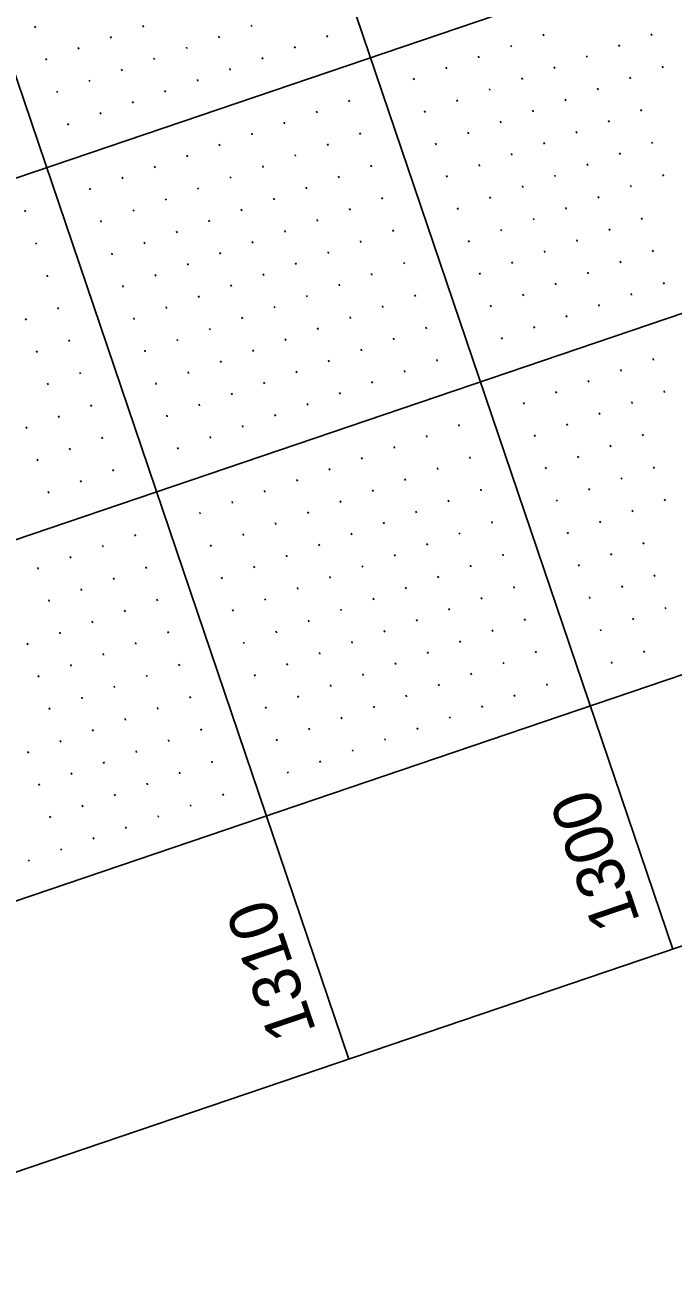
# Model space of a CAD drawing. Extents: x 2150318 to 2152065, y 143281 to 145371.
# Drawn here: x 2151548.2 to 2151642.9, y 143675.5 to 143858.1 of the extents above; entities that cross this region are included whole.
import ezdxf

# ---------------------------------------------------------------- set-up
doc = ezdxf.new("R2010")
doc.units = 0
for name, color, linetype in [('SHT_Plan_Profile_Sheet_Elev_Txt', 7, 'Continuous'), ('SHT_Profile_Grid_Major', 7, 'Continuous'), ('SHT_Profile_Grid_Minor', 7, 'Continuous'), ('SHT_Sheet_Border', 7, 'Continuous')]:
    doc.layers.add(name, color=color, linetype=linetype)

msp = doc.modelspace()

# ---------------------------------------------------------------- linework, layer by layer
at = {"layer": 'SHT_Profile_Grid_Major'}
for p, q in [((2151642.87, 143723.15), (2151136.88, 145214.66)), ((2151595.52, 143707.09), (2151089.53, 145198.6)), ((2151835.44, 143933.68), (2151361.94, 143773.05)), ((2151851.5, 143886.33), (2151378.01, 143725.7))]:
    msp.add_line(p, q, dxfattribs=at)
at = {"layer": 'SHT_Profile_Grid_Minor'}
for p, q in [((2151549.69, 143857.73), (2151549.61, 143857.97)), ((2151565.5, 143857.81), (2151565.42, 143858.05)), ((2151581.32, 143857.9), (2151581.23, 143858.14)), ((2151639.82, 143856.63), (2151639.74, 143856.86)), ((2151560.77, 143856.21), (2151560.69, 143856.44)), ((2151576.58, 143856.29), (2151576.5, 143856.53)), ((2151592.39, 143856.38), (2151592.31, 143856.61)), ((2151619.28, 143854.94), (2151619.2, 143855.17)), ((2151624.01, 143856.54), (2151623.93, 143856.78)), ((2151635.09, 143855.02), (2151635.01, 143855.26)), ((2151551.3, 143853), (2151551.22, 143853.23)), ((2151556.03, 143854.6), (2151555.95, 143854.84)), ((2151567.11, 143853.08), (2151567.03, 143853.32)), ((2151571.85, 143854.69), (2151571.76, 143854.92)), ((2151582.92, 143853.16), (2151582.84, 143853.4)), ((2151587.66, 143854.77), (2151587.58, 143855.01)), ((2151614.54, 143853.33), (2151614.46, 143853.57)), ((2151630.35, 143853.42), (2151630.27, 143853.65)), ((2151562.38, 143851.47), (2151562.3, 143851.71)), ((2151578.19, 143851.56), (2151578.11, 143851.79)), ((2151609.81, 143851.72), (2151609.73, 143851.96)), ((2151625.62, 143851.81), (2151625.54, 143852.05)), ((2151641.43, 143851.89), (2151641.35, 143852.13)), ((2151557.64, 143849.87), (2151557.56, 143850.1)), ((2151573.45, 143849.95), (2151573.37, 143850.19)), ((2151605.07, 143850.12), (2151604.99, 143850.36)), ((2151620.89, 143850.2), (2151620.8, 143850.44)), ((2151636.7, 143850.29), (2151636.62, 143850.52)), ((2151552.91, 143848.26), (2151552.83, 143848.5)), ((2151568.72, 143848.34), (2151568.64, 143848.58)), ((2151616.15, 143848.6), (2151616.07, 143848.83)), ((2151631.96, 143848.68), (2151631.88, 143848.92)), ((2151563.98, 143846.74), (2151563.9, 143846.97)), ((2151595.6, 143846.91), (2151595.52, 143847.14)), ((2151611.42, 143846.99), (2151611.33, 143847.23)), ((2151627.23, 143847.07), (2151627.15, 143847.31)), ((2151559.25, 143845.13), (2151559.17, 143845.37)), ((2151590.87, 143845.3), (2151590.79, 143845.54)), ((2151606.68, 143845.38), (2151606.6, 143845.62)), ((2151617.76, 143843.86), (2151617.68, 143844.1)), ((2151622.49, 143845.47), (2151622.41, 143845.7)), ((2151633.57, 143843.95), (2151633.49, 143844.18)), ((2151638.3, 143845.55), (2151638.22, 143845.79)), ((2151554.51, 143843.53), (2151554.43, 143843.76)), ((2151581.4, 143842.09), (2151581.32, 143842.32)), ((2151586.13, 143843.69), (2151586.05, 143843.93)), ((2151597.21, 143842.17), (2151597.13, 143842.41)), ((2151613.02, 143842.26), (2151612.94, 143842.49)), ((2151628.83, 143842.34), (2151628.75, 143842.58)), ((2151576.66, 143840.48), (2151576.58, 143840.72)), ((2151592.48, 143840.56), (2151592.4, 143840.8)), ((2151608.29, 143840.65), (2151608.21, 143840.89)), ((2151624.1, 143840.73), (2151624.02, 143840.97)), ((2151639.91, 143840.82), (2151639.83, 143841.05)), ((2151571.93, 143838.87), (2151571.85, 143839.11)), ((2151587.74, 143838.96), (2151587.66, 143839.2)), ((2151619.36, 143839.13), (2151619.28, 143839.36)), ((2151635.17, 143839.21), (2151635.09, 143839.45)), ((2151567.19, 143837.27), (2151567.11, 143837.5)), ((2151583.01, 143837.35), (2151582.93, 143837.59)), ((2151598.82, 143837.44), (2151598.74, 143837.67)), ((2151614.63, 143837.52), (2151614.55, 143837.76)), ((2151630.44, 143837.6), (2151630.36, 143837.84)), ((2151562.46, 143835.66), (2151562.38, 143835.9)), ((2151578.27, 143835.75), (2151578.19, 143835.98)), ((2151594.08, 143835.83), (2151594, 143836.07)), ((2151609.89, 143835.91), (2151609.81, 143836.15)), ((2151625.7, 143836), (2151625.62, 143836.23)), ((2151641.52, 143836.08), (2151641.43, 143836.32)), ((2151557.72, 143834.06), (2151557.64, 143834.29)), ((2151573.54, 143834.14), (2151573.46, 143834.38)), ((2151589.35, 143834.22), (2151589.27, 143834.46)), ((2151620.97, 143834.39), (2151620.89, 143834.63)), ((2151632.05, 143832.87), (2151631.96, 143833.11)), ((2151636.78, 143834.48), (2151636.7, 143834.71)), ((2151568.8, 143832.53), (2151568.72, 143832.77)), ((2151584.61, 143832.62), (2151584.53, 143832.85)), ((2151595.69, 143831.09), (2151595.61, 143831.33)), ((2151600.42, 143832.7), (2151600.34, 143832.94)), ((2151611.5, 143831.18), (2151611.42, 143831.42)), ((2151616.23, 143832.79), (2151616.15, 143833.02)), ((2151627.31, 143831.26), (2151627.23, 143831.5)), ((2151548.25, 143830.84), (2151548.17, 143831.08)), ((2151559.33, 143829.32), (2151559.25, 143829.56)), ((2151564.07, 143830.93), (2151563.99, 143831.16)), ((2151575.14, 143829.4), (2151575.06, 143829.64)), ((2151579.88, 143831.01), (2151579.8, 143831.25)), ((2151590.95, 143829.49), (2151590.87, 143829.73)), ((2151622.58, 143829.66), (2151622.5, 143829.89)), ((2151638.39, 143829.74), (2151638.31, 143829.98)), ((2151570.41, 143827.8), (2151570.33, 143828.03)), ((2151586.22, 143827.88), (2151586.14, 143828.12)), ((2151602.03, 143827.97), (2151601.95, 143828.2)), ((2151617.84, 143828.05), (2151617.76, 143828.29)), ((2151633.65, 143828.13), (2151633.57, 143828.37)), ((2151549.86, 143826.11), (2151549.78, 143826.34)), ((2151565.67, 143826.19), (2151565.59, 143826.43)), ((2151581.48, 143826.28), (2151581.4, 143826.51)), ((2151597.29, 143826.36), (2151597.21, 143826.6)), ((2151613.11, 143826.44), (2151613.03, 143826.68)), ((2151628.92, 143826.53), (2151628.84, 143826.76)), ((2151560.94, 143824.59), (2151560.86, 143824.82)), ((2151576.75, 143824.67), (2151576.67, 143824.91)), ((2151592.56, 143824.75), (2151592.48, 143824.99)), ((2151624.18, 143824.92), (2151624.1, 143825.16)), ((2151639.99, 143825.01), (2151639.91, 143825.24)), ((2151572.01, 143823.06), (2151571.93, 143823.3)), ((2151587.82, 143823.15), (2151587.74, 143823.38)), ((2151603.64, 143823.23), (2151603.56, 143823.47)), ((2151619.45, 143823.32), (2151619.37, 143823.55)), ((2151635.26, 143823.4), (2151635.18, 143823.64)), ((2151551.47, 143821.37), (2151551.39, 143821.61)), ((2151567.28, 143821.46), (2151567.2, 143821.69)), ((2151583.09, 143821.54), (2151583.01, 143821.78)), ((2151598.9, 143821.62), (2151598.82, 143821.86)), ((2151614.71, 143821.71), (2151614.63, 143821.95)), ((2151625.79, 143820.19), (2151625.71, 143820.42)), ((2151630.52, 143821.79), (2151630.44, 143822.03)), ((2151641.6, 143820.27), (2151641.52, 143820.51)), ((2151562.54, 143819.85), (2151562.46, 143820.09)), ((2151573.62, 143818.33), (2151573.54, 143818.57)), ((2151578.35, 143819.93), (2151578.27, 143820.17)), ((2151589.43, 143818.41), (2151589.35, 143818.65)), ((2151594.17, 143820.02), (2151594.09, 143820.26)), ((2151605.24, 143818.5), (2151605.16, 143818.73)), ((2151621.05, 143818.58), (2151620.97, 143818.82)), ((2151636.86, 143818.66), (2151636.78, 143818.9)), ((2151553.07, 143816.64), (2151552.99, 143816.87)), ((2151568.88, 143816.72), (2151568.8, 143816.96)), ((2151584.7, 143816.81), (2151584.62, 143817.04)), ((2151600.51, 143816.89), (2151600.43, 143817.13)), ((2151616.32, 143816.97), (2151616.24, 143817.21)), ((2151632.13, 143817.06), (2151632.05, 143817.29)), ((2151548.34, 143815.03), (2151548.26, 143815.27)), ((2151564.15, 143815.12), (2151564.07, 143815.35)), ((2151579.96, 143815.2), (2151579.88, 143815.44)), ((2151595.77, 143815.28), (2151595.69, 143815.52)), ((2151627.39, 143815.45), (2151627.31, 143815.69)), ((2151575.23, 143813.59), (2151575.15, 143813.83)), ((2151591.04, 143813.68), (2151590.96, 143813.91)), ((2151606.85, 143813.76), (2151606.77, 143814)), ((2151622.66, 143813.85), (2151622.58, 143814.08)), ((2151554.68, 143811.9), (2151554.6, 143812.14)), ((2151570.49, 143811.99), (2151570.41, 143812.22)), ((2151586.3, 143812.07), (2151586.22, 143812.31)), ((2151602.11, 143812.16), (2151602.03, 143812.39)), ((2151617.92, 143812.24), (2151617.84, 143812.48)), ((2151549.94, 143810.3), (2151549.86, 143810.53)), ((2151565.76, 143810.38), (2151565.68, 143810.62)), ((2151581.57, 143810.46), (2151581.49, 143810.7)), ((2151597.38, 143810.55), (2151597.3, 143810.79)), ((2151640.08, 143809.19), (2151640, 143809.43)), ((2151576.83, 143808.86), (2151576.75, 143809.1)), ((2151587.91, 143807.34), (2151587.83, 143807.57)), ((2151592.64, 143808.94), (2151592.56, 143809.18)), ((2151603.72, 143807.42), (2151603.64, 143807.66)), ((2151608.45, 143809.03), (2151608.37, 143809.26)), ((2151635.34, 143807.59), (2151635.26, 143807.82)), ((2151551.55, 143805.56), (2151551.47, 143805.8)), ((2151556.29, 143807.17), (2151556.21, 143807.4)), ((2151567.36, 143805.65), (2151567.28, 143805.88)), ((2151572.1, 143807.25), (2151572.02, 143807.49)), ((2151583.17, 143805.73), (2151583.09, 143805.97)), ((2151598.98, 143805.81), (2151598.9, 143806.05)), ((2151630.61, 143805.98), (2151630.53, 143806.22)), ((2151578.44, 143804.12), (2151578.36, 143804.36)), ((2151594.25, 143804.21), (2151594.17, 143804.44)), ((2151625.87, 143804.38), (2151625.79, 143804.61)), ((2151641.68, 143804.46), (2151641.6, 143804.7)), ((2151557.89, 143802.43), (2151557.81, 143802.67)), ((2151573.7, 143802.52), (2151573.62, 143802.75)), ((2151589.51, 143802.6), (2151589.43, 143802.84)), ((2151621.14, 143802.77), (2151621.06, 143803.01)), ((2151636.95, 143802.85), (2151636.87, 143803.09)), ((2151553.16, 143800.83), (2151553.08, 143801.06)), ((2151568.97, 143800.91), (2151568.89, 143801.15)), ((2151584.78, 143800.99), (2151584.7, 143801.23)), ((2151632.21, 143801.25), (2151632.13, 143801.48)), ((2151548.42, 143799.22), (2151548.34, 143799.46)), ((2151580.04, 143799.39), (2151579.96, 143799.63)), ((2151611.67, 143799.56), (2151611.59, 143799.79)), ((2151627.48, 143799.64), (2151627.4, 143799.88)), ((2151559.5, 143797.7), (2151559.42, 143797.93)), ((2151575.31, 143797.78), (2151575.23, 143798.02)), ((2151602.2, 143796.34), (2151602.12, 143796.58)), ((2151606.93, 143797.95), (2151606.85, 143798.19)), ((2151622.74, 143798.03), (2151622.66, 143798.27)), ((2151633.82, 143796.51), (2151633.74, 143796.75)), ((2151638.55, 143798.12), (2151638.47, 143798.35)), ((2151554.76, 143796.09), (2151554.68, 143796.33)), ((2151570.57, 143796.18), (2151570.49, 143796.41)), ((2151597.46, 143794.74), (2151597.38, 143794.97)), ((2151613.27, 143794.82), (2151613.19, 143795.06)), ((2151629.08, 143794.91), (2151629, 143795.14)), ((2151550.03, 143794.49), (2151549.95, 143794.72)), ((2151561.1, 143792.96), (2151561.02, 143793.2)), ((2151592.73, 143793.13), (2151592.65, 143793.37)), ((2151608.54, 143793.22), (2151608.46, 143793.45)), ((2151624.35, 143793.3), (2151624.27, 143793.54)), ((2151640.16, 143793.38), (2151640.08, 143793.62)), ((2151556.37, 143791.36), (2151556.29, 143791.59)), ((2151587.99, 143791.52), (2151587.91, 143791.76)), ((2151603.8, 143791.61), (2151603.72, 143791.85)), ((2151635.43, 143791.78), (2151635.35, 143792.01)), ((2151551.64, 143789.75), (2151551.55, 143789.99)), ((2151583.26, 143789.92), (2151583.18, 143790.16)), ((2151599.07, 143790), (2151598.99, 143790.24)), ((2151614.88, 143790.09), (2151614.8, 143790.32)), ((2151630.69, 143790.17), (2151630.61, 143790.41)), ((2151578.52, 143788.31), (2151578.44, 143788.55)), ((2151594.33, 143788.4), (2151594.25, 143788.63)), ((2151610.14, 143788.48), (2151610.06, 143788.72)), ((2151625.96, 143788.56), (2151625.88, 143788.8)), ((2151641.77, 143788.65), (2151641.69, 143788.89)), ((2151573.79, 143786.71), (2151573.71, 143786.94)), ((2151589.6, 143786.79), (2151589.52, 143787.03)), ((2151605.41, 143786.87), (2151605.33, 143787.11)), ((2151632.3, 143785.44), (2151632.22, 143785.67)), ((2151637.03, 143787.04), (2151636.95, 143787.28)), ((2151580.13, 143783.58), (2151580.05, 143783.81)), ((2151584.86, 143785.18), (2151584.78, 143785.42)), ((2151595.94, 143783.66), (2151595.86, 143783.9)), ((2151600.67, 143785.27), (2151600.59, 143785.5)), ((2151611.75, 143783.75), (2151611.67, 143783.98)), ((2151616.49, 143785.35), (2151616.41, 143785.59)), ((2151627.56, 143783.83), (2151627.48, 143784.07)), ((2151559.58, 143781.89), (2151559.5, 143782.12)), ((2151564.32, 143783.49), (2151564.24, 143783.73)), ((2151575.39, 143781.97), (2151575.31, 143782.21)), ((2151591.21, 143782.06), (2151591.12, 143782.29)), ((2151607.02, 143782.14), (2151606.94, 143782.38)), ((2151638.64, 143782.31), (2151638.56, 143782.54)), ((2151554.85, 143780.28), (2151554.77, 143780.52)), ((2151586.47, 143780.45), (2151586.39, 143780.69)), ((2151602.28, 143780.53), (2151602.2, 143780.77)), ((2151618.09, 143780.62), (2151618.01, 143780.85)), ((2151633.9, 143780.7), (2151633.82, 143780.94)), ((2151550.11, 143778.67), (2151550.03, 143778.91)), ((2151565.92, 143778.76), (2151565.84, 143779)), ((2151581.74, 143778.84), (2151581.65, 143779.08)), ((2151597.55, 143778.93), (2151597.47, 143779.16)), ((2151613.36, 143779.01), (2151613.28, 143779.25)), ((2151629.17, 143779.09), (2151629.09, 143779.33)), ((2151561.19, 143777.15), (2151561.11, 143777.39)), ((2151577, 143777.24), (2151576.92, 143777.47)), ((2151592.81, 143777.32), (2151592.73, 143777.56)), ((2151608.62, 143777.4), (2151608.54, 143777.64)), ((2151640.24, 143777.57), (2151640.16, 143777.81)), ((2151556.45, 143775.55), (2151556.37, 143775.78)), ((2151588.08, 143775.71), (2151588, 143775.95)), ((2151603.89, 143775.8), (2151603.81, 143776.03)), ((2151619.7, 143775.88), (2151619.62, 143776.12)), ((2151635.51, 143775.97), (2151635.43, 143776.2)), ((2151551.72, 143773.94), (2151551.64, 143774.18)), ((2151567.53, 143774.02), (2151567.45, 143774.26)), ((2151583.34, 143774.11), (2151583.26, 143774.34)), ((2151599.15, 143774.19), (2151599.07, 143774.43)), ((2151610.23, 143772.67), (2151610.15, 143772.91)), ((2151614.96, 143774.28), (2151614.88, 143774.51)), ((2151630.77, 143774.36), (2151630.69, 143774.6)), ((2151641.85, 143772.84), (2151641.77, 143773.07)), ((2151558.06, 143770.81), (2151557.98, 143771.05)), ((2151562.8, 143772.42), (2151562.72, 143772.65)), ((2151578.61, 143772.5), (2151578.53, 143772.74)), ((2151589.68, 143770.98), (2151589.6, 143771.22)), ((2151594.42, 143772.59), (2151594.34, 143772.82)), ((2151605.49, 143771.06), (2151605.41, 143771.3)), ((2151621.31, 143771.15), (2151621.22, 143771.38)), ((2151637.12, 143771.23), (2151637.04, 143771.47)), ((2151553.33, 143769.2), (2151553.25, 143769.44)), ((2151569.14, 143769.29), (2151569.06, 143769.53)), ((2151584.95, 143769.37), (2151584.87, 143769.61)), ((2151600.76, 143769.46), (2151600.68, 143769.69)), ((2151616.57, 143769.54), (2151616.49, 143769.78)), ((2151632.38, 143769.62), (2151632.3, 143769.86)), ((2151548.59, 143767.6), (2151548.51, 143767.83)), ((2151564.4, 143767.68), (2151564.32, 143767.92)), ((2151580.21, 143767.77), (2151580.13, 143768)), ((2151596.02, 143767.85), (2151595.94, 143768.09)), ((2151611.84, 143767.93), (2151611.75, 143768.17)), ((2151559.67, 143766.08), (2151559.59, 143766.31)), ((2151591.29, 143766.24), (2151591.21, 143766.48)), ((2151607.1, 143766.33), (2151607.02, 143766.56)), ((2151622.91, 143766.41), (2151622.83, 143766.65)), ((2151638.72, 143766.5), (2151638.64, 143766.73)), ((2151554.93, 143764.47), (2151554.85, 143764.71)), ((2151570.74, 143764.55), (2151570.66, 143764.79)), ((2151586.55, 143764.64), (2151586.47, 143764.87)), ((2151602.37, 143764.72), (2151602.28, 143764.96)), ((2151618.18, 143764.81), (2151618.1, 143765.04)), ((2151633.99, 143764.89), (2151633.91, 143765.13)), ((2151550.2, 143762.86), (2151550.12, 143763.1)), ((2151566.01, 143762.95), (2151565.93, 143763.18)), ((2151581.82, 143763.03), (2151581.74, 143763.27)), ((2151597.63, 143763.12), (2151597.55, 143763.35)), ((2151613.44, 143763.2), (2151613.36, 143763.44)), ((2151624.52, 143761.68), (2151624.44, 143761.91)), ((2151561.27, 143761.34), (2151561.19, 143761.58)), ((2151588.16, 143759.9), (2151588.08, 143760.14)), ((2151592.9, 143761.51), (2151592.82, 143761.75)), ((2151603.97, 143759.99), (2151603.89, 143760.22)), ((2151608.71, 143761.59), (2151608.63, 143761.83)), ((2151619.78, 143760.07), (2151619.7, 143760.31)), ((2151551.8, 143758.13), (2151551.72, 143758.37)), ((2151556.54, 143759.73), (2151556.46, 143759.97)), ((2151567.61, 143758.21), (2151567.53, 143758.45)), ((2151572.35, 143759.82), (2151572.27, 143760.06)), ((2151583.43, 143758.3), (2151583.35, 143758.53)), ((2151599.24, 143758.38), (2151599.16, 143758.62)), ((2151615.05, 143758.46), (2151614.97, 143758.7)), ((2151562.88, 143756.61), (2151562.8, 143756.84)), ((2151594.5, 143756.77), (2151594.42, 143757.01)), ((2151610.31, 143756.86), (2151610.23, 143757.09)), ((2151558.14, 143755), (2151558.06, 143755.24)), ((2151573.96, 143755.08), (2151573.88, 143755.32)), ((2151589.77, 143755.17), (2151589.69, 143755.4)), ((2151605.58, 143755.25), (2151605.5, 143755.49)), ((2151553.41, 143753.39), (2151553.33, 143753.63)), ((2151569.22, 143753.48), (2151569.14, 143753.71)), ((2151585.03, 143753.56), (2151584.95, 143753.8)), ((2151600.84, 143753.65), (2151600.76, 143753.88)), ((2151548.67, 143751.79), (2151548.59, 143752.02)), ((2151564.49, 143751.87), (2151564.41, 143752.11)), ((2151596.11, 143752.04), (2151596.03, 143752.28)), ((2151559.75, 143750.26), (2151559.67, 143750.5)), ((2151575.56, 143750.35), (2151575.48, 143750.59)), ((2151591.37, 143750.43), (2151591.29, 143750.67)), ((2151550.28, 143747.05), (2151550.2, 143747.29)), ((2151555.02, 143748.66), (2151554.94, 143748.9)), ((2151566.09, 143747.14), (2151566.01, 143747.37)), ((2151570.83, 143748.74), (2151570.75, 143748.98)), ((2151586.64, 143748.83), (2151586.56, 143749.06)), ((2151561.36, 143745.53), (2151561.28, 143745.77)), ((2151577.17, 143745.61), (2151577.09, 143745.85)), ((2151556.62, 143743.92), (2151556.54, 143744.16)), ((2151572.43, 143744.01), (2151572.35, 143744.24)), ((2151551.89, 143742.32), (2151551.81, 143742.55)), ((2151567.7, 143742.4), (2151567.62, 143742.64)), ((2151562.96, 143740.79), (2151562.88, 143741.03)), ((2151558.23, 143739.19), (2151558.15, 143739.43)), ((2151553.49, 143737.58), (2151553.41, 143737.82)), ((2151548.76, 143735.98), (2151548.68, 143736.21))]:
    msp.add_line(p, q, dxfattribs=at)
at = {"layer": 'SHT_Sheet_Border'}
msp.add_line((2151867.57, 143838.98), (2151394.07, 143678.35), dxfattribs=at)
msp.add_lwpolyline([(2150901.85, 143471.77), (2150395.86, 144963.28), (2151390.2, 145300.6), (2151896.19, 143809.09)], close=True, dxfattribs=at)

# ---------------------------------------------------------------- texts
at = {"layer": 'SHT_Plan_Profile_Sheet_Elev_Txt'}
for s, p in [('1300', (2151638.14, 143727.25)), ('1310', (2151590.79, 143711.19))]:
    msp.add_text(s, height=7, rotation=108.7393, dxfattribs=at).set_placement(p)

doc.saveas('drawing.dxf')
